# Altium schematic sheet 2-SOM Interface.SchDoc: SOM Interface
size B; CompanyName: NextGen RF Design; Address1: 2130 Howard Drive W; Address2: North Mankato, MN 56003; Address3: www.nextgenrf.com; Revision: 2; SheetNumber: 2; SheetTotal: 7; ProjName: BytePipe X9002_HDK
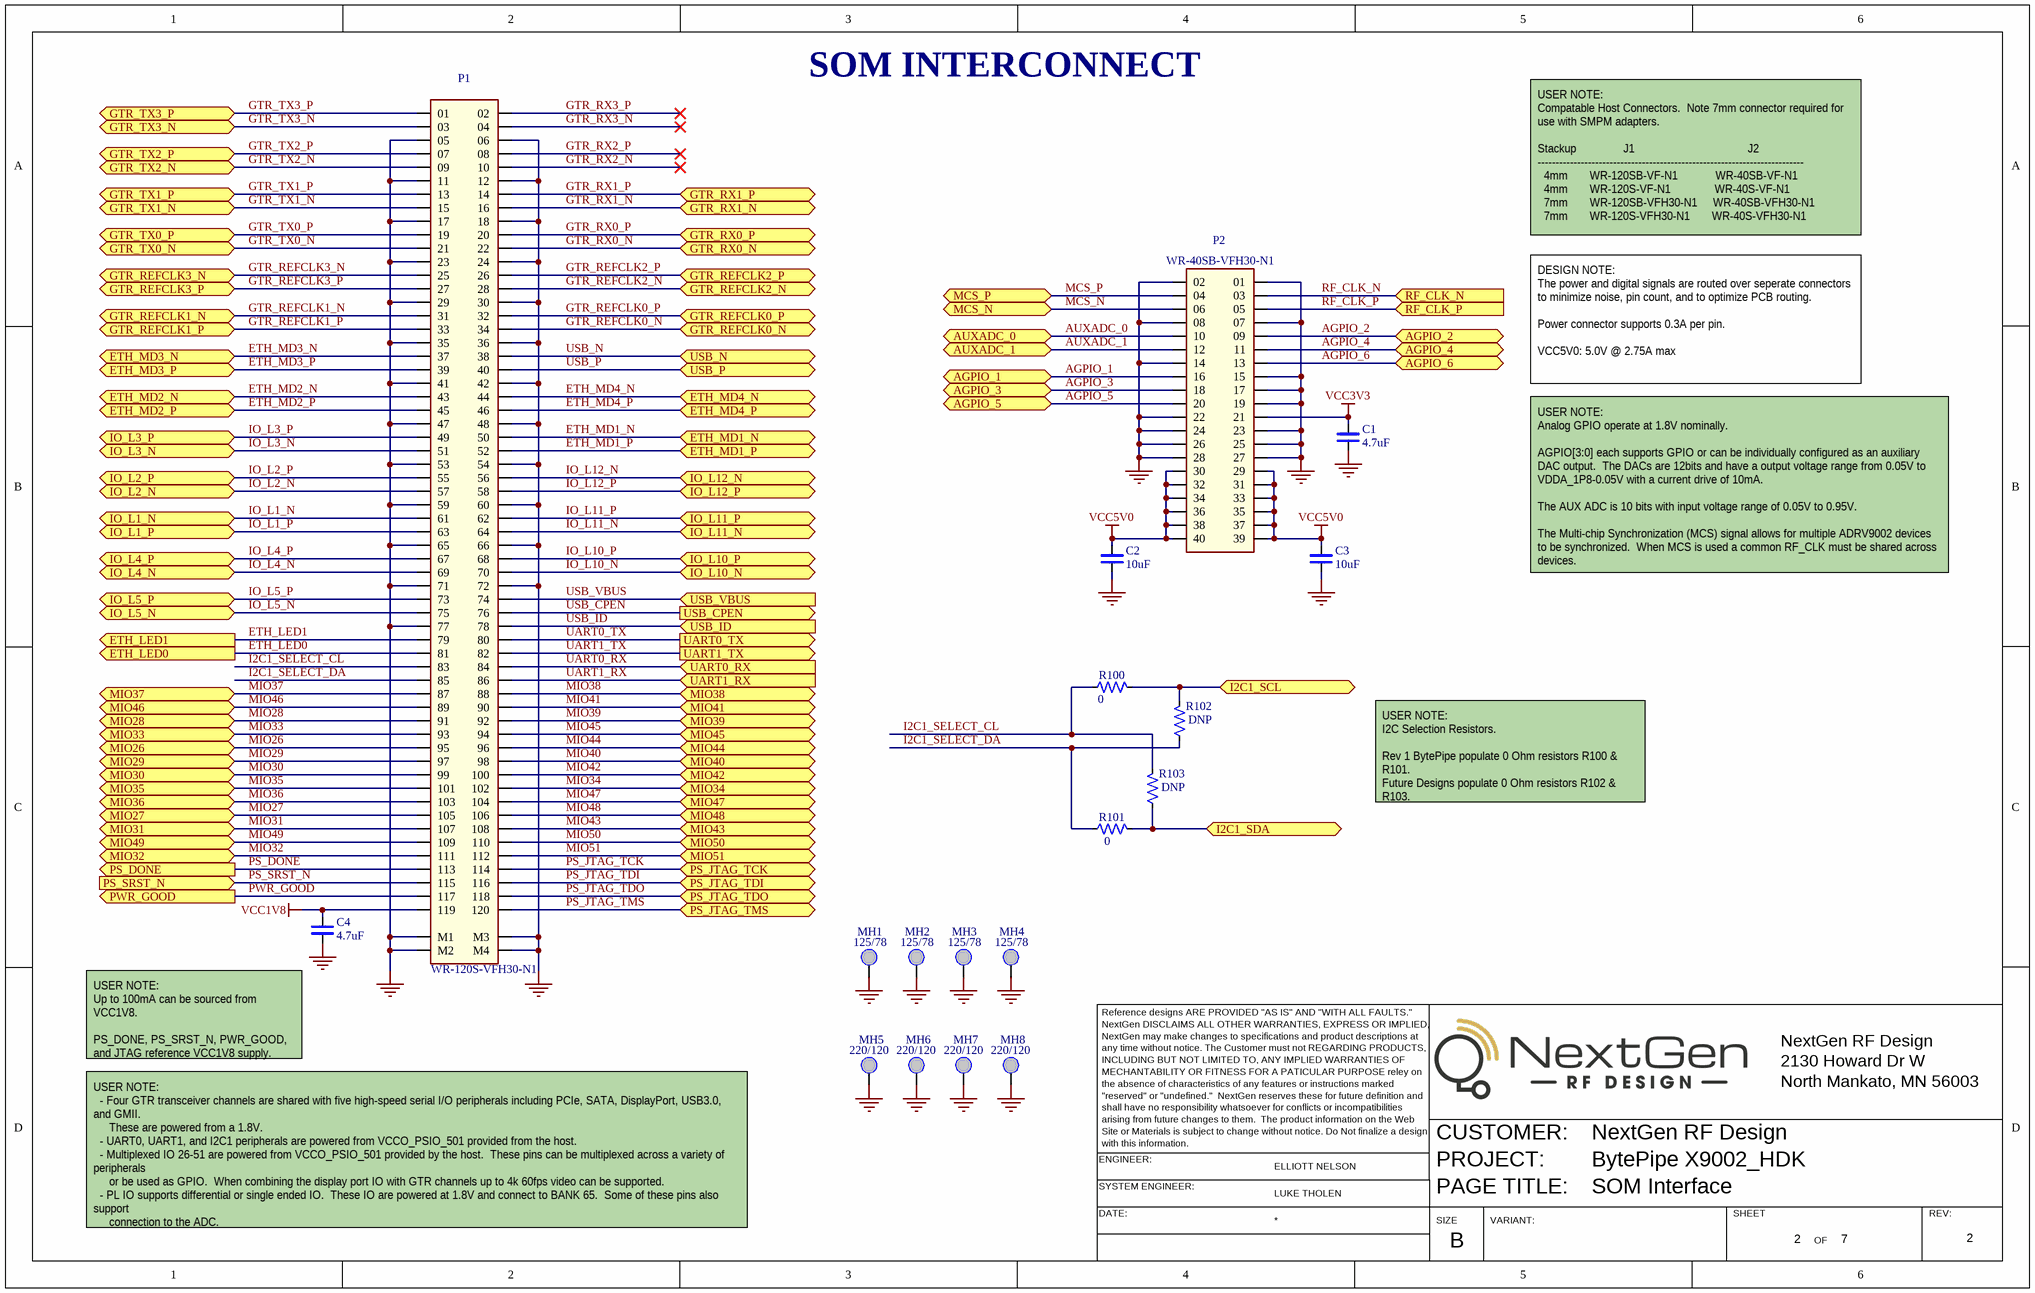
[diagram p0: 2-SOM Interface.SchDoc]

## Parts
C1  value 4.7uF  [SM/0402/CAP]  (hidden comment: CAP_CERAMIC_0402)
C2  value 10uF  [SM/0402/CAP]  (hidden comment: CAP_CERAMIC_0402)
C3  value 10uF  [SM/0402/CAP]  (hidden comment: CAP_CERAMIC_0402)
C4  value 4.7uF  [SM/0402/CAP]  (hidden comment: CAP_CERAMIC_0402)
MH1  HOLE_PTH_125/78  [MTG125/78]  (value not drawn)  (no BOM)
MH2  HOLE_PTH_125/78  [MTG125/78]  (value not drawn)  (no BOM)
MH3  HOLE_PTH_125/78  [MTG125/78]  (value not drawn)  (no BOM)
MH4  HOLE_PTH_125/78  [MTG125/78]  (value not drawn)  (no BOM)
MH5  HOLE_PTH_220/120  [MTG220/120]  (value not drawn)  (no BOM)
MH6  HOLE_PTH_220/120  [MTG220/120]  (value not drawn)  (no BOM)
MH7  HOLE_PTH_220/120  [MTG220/120]  (value not drawn)  (no BOM)
MH8  HOLE_PTH_220/120  [MTG220/120]  (value not drawn)  (no BOM)
P1  value WR-120S-VFH30-N1  [SM/CON/JAE/WR-120S-VFH30-N1]  (hidden comment: WR-120S-VFH30-N1‎)
P2  value WR-40SB-VFH30-N1  [SM/CON/JAE/WR-40SB-VFH30-N1]  (hidden comment: WR-40SB-VFH30-N1‎)
R100  value 0  [SM/0402/RES]  (hidden comment: RES_0402_A)
R101  value 0  [SM/0402/RES]  (hidden comment: RES_0402_A)
R102  value DNP  [SM/0402/RES]  (hidden comment: RES_0402_A)
R103  value DNP  [SM/0402/RES]  (hidden comment: RES_0402_A)

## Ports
AGPIO_1 (bidir), AGPIO_2 (bidir), AGPIO_3 (bidir), AGPIO_4 (bidir), AGPIO_5 (bidir), AGPIO_6 (bidir), AUXADC_0 (bidir), AUXADC_1 (bidir), ETH_LED0 (out), ETH_LED1 (out), ETH_MD1_N (bidir), ETH_MD1_P (bidir), ETH_MD2_N (bidir), ETH_MD2_P (bidir), ETH_MD3_N (bidir), ETH_MD3_P (bidir), ETH_MD4_N (bidir), ETH_MD4_P (bidir), GTR_REFCLK0_N (bidir), GTR_REFCLK0_P (bidir), GTR_REFCLK1_N (bidir), GTR_REFCLK1_P (bidir), GTR_REFCLK2_N (bidir), GTR_REFCLK2_P (bidir), GTR_REFCLK3_N (bidir), GTR_REFCLK3_P (bidir), GTR_RX0_N (bidir), GTR_RX0_P (bidir), GTR_RX1_N (bidir), GTR_RX1_P (bidir), GTR_TX0_N (bidir), GTR_TX0_P (bidir), GTR_TX1_N (bidir), GTR_TX1_P (bidir), GTR_TX2_N (bidir), GTR_TX2_P (bidir), GTR_TX3_N (bidir), GTR_TX3_P (bidir), I2C1_SCL (bidir), I2C1_SDA (bidir), IO_L1_N (bidir), IO_L1_P (bidir), IO_L2_N (bidir), IO_L2_P (bidir), IO_L3_N (bidir), IO_L3_P (bidir), IO_L4_N (bidir), IO_L4_P (bidir), IO_L5_N (bidir), IO_L5_P (bidir), IO_L10_N (bidir), IO_L10_P (bidir), IO_L11_N (bidir), IO_L11_P (bidir), IO_L12_N (bidir), IO_L12_P (bidir), MCS_N (bidir), MCS_P (bidir), MIO26 (bidir), MIO27 (bidir), MIO28 (bidir), MIO29 (bidir), MIO30 (bidir), MIO31 (bidir), MIO32 (bidir), MIO33 (bidir), MIO34 (bidir), MIO35 (bidir), MIO36 (bidir), MIO37 (bidir), MIO38 (bidir), MIO39 (bidir), MIO40 (bidir), MIO41 (bidir), MIO42 (bidir), MIO43 (bidir), MIO44 (bidir), MIO45 (bidir), MIO46 (bidir), MIO47 (bidir), MIO48 (bidir), MIO49 (bidir), MIO50 (bidir), MIO51 (bidir), PS_DONE (out), PS_JTAG_TCK (bidir), PS_JTAG_TDI (bidir), PS_JTAG_TDO (bidir), PS_JTAG_TMS (bidir), PS_SRST_N (in), PWR_GOOD (out), RF_CLK_N (in), RF_CLK_P (in), UART0_RX (in), UART0_TX (out), UART1_RX (in), UART1_TX (out), USB_CPEN (out), USB_ID (in), USB_N (bidir), USB_P (bidir), USB_VBUS (in)

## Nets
GND: C1.2(N2) C2.2(N2) C3.2(N2) C4.2(N2) MH1.1(N1) MH2.1(N1) MH3.1(N1) MH4.1(N1) MH5.1(N1) MH6.1(N1) MH7.1(N1) MH8.1(N1) P1.05 P1.06 P1.11 P1.12 P1.17 P1.18 P1.23 P1.24 P1.29 P1.30 P1.35 P1.36 P1.41 P1.42 P1.47 P1.48 P1.53 P1.54 P1.59 P1.60 P1.65 P1.66 P1.71 P1.72 P1.77 P1.M1 P1.M2 P1.M3 P1.M4 P2.01 P2.02 P2.07 P2.08 P2.14 P2.15 P2.17 P2.19 P2.22 P2.23 P2.24 P2.25 P2.26 P2.27 P2.28
VCC1V8: C4.1(N1) P1.119
VCC3V3: C1.1(N1) P2.21
VCC5V0: C2.1(N1) C3.1(N1) P2.29 P2.30 P2.31 P2.32 P2.33 P2.34 P2.35 P2.36 P2.37 P2.38 P2.39 P2.40
AGPIO_1: P2.16 ; port AGPIO_1
AGPIO_2: P2.09 ; port AGPIO_2
AGPIO_3: P2.18 ; port AGPIO_3
AGPIO_4: P2.11 ; port AGPIO_4
AGPIO_5: P2.20 ; port AGPIO_5
AGPIO_6: P2.13 ; port AGPIO_6
AUXADC_0: P2.10 ; port AUXADC_0
AUXADC_1: P2.12 ; port AUXADC_1
ETH_LED0: P1.81 ; port ETH_LED0
ETH_LED1: P1.79 ; port ETH_LED1
ETH_MD1_N: P1.50 ; port ETH_MD1_N
ETH_MD1_P: P1.52 ; port ETH_MD1_P
ETH_MD2_N: P1.43 ; port ETH_MD2_N
ETH_MD2_P: P1.45 ; port ETH_MD2_P
ETH_MD3_N: P1.37 ; port ETH_MD3_N
ETH_MD3_P: P1.39 ; port ETH_MD3_P
ETH_MD4_N: P1.44 ; port ETH_MD4_N
ETH_MD4_P: P1.46 ; port ETH_MD4_P
GTR_REFCLK0_N: P1.34 ; port GTR_REFCLK0_N
GTR_REFCLK0_P: P1.32 ; port GTR_REFCLK0_P
GTR_REFCLK1_N: P1.31 ; port GTR_REFCLK1_N
GTR_REFCLK1_P: P1.33 ; port GTR_REFCLK1_P
GTR_REFCLK2_N: P1.28 ; port GTR_REFCLK2_N
GTR_REFCLK2_P: P1.26 ; port GTR_REFCLK2_P
GTR_REFCLK3_N: P1.25 ; port GTR_REFCLK3_N
GTR_REFCLK3_P: P1.27 ; port GTR_REFCLK3_P
GTR_RX0_N: P1.22 ; port GTR_RX0_N
GTR_RX0_P: P1.20 ; port GTR_RX0_P
GTR_RX1_N: P1.16 ; port GTR_RX1_N
GTR_RX1_P: P1.14 ; port GTR_RX1_P
GTR_RX2_N: P1.10
GTR_RX2_P: P1.08
GTR_RX3_N: P1.04
GTR_RX3_P: P1.02
GTR_TX0_N: P1.21 ; port GTR_TX0_N
GTR_TX0_P: P1.19 ; port GTR_TX0_P
GTR_TX1_N: P1.15 ; port GTR_TX1_N
GTR_TX1_P: P1.13 ; port GTR_TX1_P
GTR_TX2_N: P1.09 ; port GTR_TX2_N
GTR_TX2_P: P1.07 ; port GTR_TX2_P
GTR_TX3_N: P1.03 ; port GTR_TX3_N
GTR_TX3_P: P1.01 ; port GTR_TX3_P
I2C1_SCL: R100.1 R102.1 ; port I2C1_SCL
I2C1_SDA: R101.1 R103.2 ; port I2C1_SDA
I2C1_SELECT_CL: P1.83 R100.2 R103.1
I2C1_SELECT_DA: P1.85 R101.2 R102.2
IO_L1_N: P1.61 ; port IO_L1_N
IO_L1_P: P1.63 ; port IO_L1_P
IO_L2_N: P1.57 ; port IO_L2_N
IO_L2_P: P1.55 ; port IO_L2_P
IO_L3_N: P1.51 ; port IO_L3_N
IO_L3_P: P1.49 ; port IO_L3_P
IO_L4_N: P1.69 ; port IO_L4_N
IO_L4_P: P1.67 ; port IO_L4_P
IO_L5_N: P1.75 ; port IO_L5_N
IO_L5_P: P1.73 ; port IO_L5_P
IO_L10_N: P1.70 ; port IO_L10_N
IO_L10_P: P1.68 ; port IO_L10_P
IO_L11_N: P1.64 ; port IO_L11_N
IO_L11_P: P1.62 ; port IO_L11_P
IO_L12_N: P1.56 ; port IO_L12_N
IO_L12_P: P1.58 ; port IO_L12_P
MCS_N: P2.06 ; port MCS_N
MCS_P: P2.04 ; port MCS_P
MIO26: P1.95 ; port MIO26
MIO27: P1.105 ; port MIO27
MIO28: P1.91 ; port MIO28
MIO29: P1.97 ; port MIO29
MIO30: P1.99 ; port MIO30
MIO31: P1.107 ; port MIO31
MIO32: P1.111 ; port MIO32
MIO33: P1.93 ; port MIO33
MIO34: P1.102 ; port MIO34
MIO35: P1.101 ; port MIO35
MIO36: P1.103 ; port MIO36
MIO37: P1.87 ; port MIO37
MIO38: P1.88 ; port MIO38
MIO39: P1.92 ; port MIO39
MIO40: P1.98 ; port MIO40
MIO41: P1.90 ; port MIO41
MIO42: P1.100 ; port MIO42
MIO43: P1.108 ; port MIO43
MIO44: P1.96 ; port MIO44
MIO45: P1.94 ; port MIO45
MIO46: P1.89 ; port MIO46
MIO47: P1.104 ; port MIO47
MIO48: P1.106 ; port MIO48
MIO49: P1.109 ; port MIO49
MIO50: P1.110 ; port MIO50
MIO51: P1.112 ; port MIO51
PS_DONE: P1.113 ; port PS_DONE
PS_JTAG_TCK: P1.114 ; port PS_JTAG_TCK
PS_JTAG_TDI: P1.116 ; port PS_JTAG_TDI
PS_JTAG_TDO: P1.118 ; port PS_JTAG_TDO
PS_JTAG_TMS: P1.120 ; port PS_JTAG_TMS
PS_SRST_N: P1.115 ; port PS_SRST_N
PWR_GOOD: P1.117 ; port PWR_GOOD
RF_CLK_N: P2.03 ; port RF_CLK_N
RF_CLK_P: P2.05 ; port RF_CLK_P
UART0_RX: P1.84 ; port UART0_RX
UART0_TX: P1.80 ; port UART0_TX
UART1_RX: P1.86 ; port UART1_RX
UART1_TX: P1.82 ; port UART1_TX
USB_CPEN: P1.76 ; port USB_CPEN
USB_ID: P1.78 ; port USB_ID
USB_N: P1.38 ; port USB_N
USB_P: P1.40 ; port USB_P
USB_VBUS: P1.74 ; port USB_VBUS

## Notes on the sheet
- SOM INTERCONNECT
- USER NOTE:
  Compatable Host Connectors.  Note 7mm connector required for use with SMPM adapters.
  Stackup               J1                                    J2
  --------------------------------------------------------------------------
  4mm       WR-120SB-VF-N1            WR-40SB-VF-N1
  4mm       WR-120S-VF-N1              WR-40S-VF-N1
  7mm       WR-120SB-VFH30-N1     WR-40SB-VFH30-N1
  7mm       WR-120S-VFH30-N1       WR-40S-VFH30-N1
- DESIGN NOTE:
  The power and digital signals are routed over seperate connectors to minimize noise, pin count, and to optimize PCB routing.
  Power connector supports 0.3A per pin.
  VCC5V0: 5.0V @ 2.75A max
- USER NOTE:
  Analog GPIO operate at 1.8V nominally.
  AGPIO[3:0] each supports GPIO or can be individually configured as an auxiliary DAC output.  The DACs are 12bits and have a output voltage range from 0.05V to VDDA_1P8-0.05V with a current drive of 10mA.
  The AUX ADC is 10 bits with input voltage range of 0.05V to 0.95V.
  The Multi-chip Synchronization (MCS) signal allows for multiple ADRV9002 devices to be synchronized.  When MCS is used a common RF_CLK must be shared across devices.
- USER NOTE:
  I2C Selection Resistors.
  Rev 1 BytePipe populate 0 Ohm resistors R100 & R101.
  Future Designs populate 0 Ohm resistors R102 & R103.
- Reference designs ARE PROVIDED "AS IS" AND "WITH ALL FAULTS."
- NextGen DISCLAIMS ALL OTHER WARRANTIES, EXPRESS OR IMPLIED,
- NextGen may make changes to specifications and product descriptions at
- NextGen RF Design
- (near C4) USER NOTE:
  Up to 100mA can be sourced from VCC1V8.
  PS_DONE, PS_SRST_N, PWR_GOOD, and JTAG reference VCC1V8 supply.
- any time without notice. The Customer must not REGARDING PRODUCTS,
- INCLUDING BUT NOT LIMITED TO, ANY IMPLIED WARRANTIES OF
- MECHANTABILITY OR FITNESS FOR A PATICULAR PURPOSE reley on
- "reserved" or "undefined."  NextGen reserves these for future definition and
- the absence of characteristics of any features or instructions marked
- shall have no responsibility whatsoever for conflicts or incompatibilities
- 2130 Howard Dr W
- North Mankato, MN 56003
- ENGINEER:
- Site or Materials is subject to change without notice. Do Not finalize a design
- with this information.
- arising from future changes to them.  The product information on the Web
- ELLIOTT NELSON
- CUSTOMER:
- PROJECT:
- USER NOTE:
  - Four GTR transceiver channels are shared with five high-speed serial I/O peripherals including PCIe, SATA, DisplayPort, USB3.0, and GMII.
  These are powered from a 1.8V.
  - UART0, UART1, and I2C1 peripherals are powered from VCCO_PSIO_501 provided from the host.
  - Multiplexed IO 26-51 are powered from VCCO_PSIO_501 provided by the host.  These pins can be multiplexed across a variety of peripherals
  or be used as GPIO.  When combining the display port IO with GTR channels up to 4k 60fps video can be supported.
  - PL IO supports differential or single ended IO.  These IO are powered at 1.8V and connect to BANK 65.  Some of these pins also support
  connection to the ADC.
  - USB OTG signals support USB2.0 host or device.  They can be combined with GTR channels to support USB 3.0.
- SYSTEM ENGINEER:
- DATE:
- LUKE THOLEN
- SIZE
- PAGE TITLE:
- VARIANT:
- SHEET
- OF
- REV:
- B

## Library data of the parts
C1 C4 = CAP_CERAMIC_0402: CAP CER 4.7UF 10V X5R 0402; TOL: ±20%; OEM#: CL05A475MP5NRNC; OEM NAME: Samsung
C2 C3 = CAP_CERAMIC_0402: 10µF ±20% 10V Ceramic Capacitor X5R 0402 (1005 Metric); OEM#: CL05A106MP8NUB8; OEM NAME: Samsung
MH1-MH4 = HOLE_PTH_125/78: 125 mil pad / 78 mil hole
MH5-MH8 = HOLE_PTH_220/120: 220 mil pad / 120 mil hole (#4 Pan Head Screw)
P1 = CON_JAE_WR-120S-VFH30-N1: 0.5 mm pitch, 120 Position Connector Receptacle, Center Strip Contacts Surface Mount Gold.; OEM NAME: JAE
P2 = CON_JAE_WR-40SB-VFH30-N1: 0.5 mm pitch, 40 Position Connector Receptacle, Center Strip Contacts Surface Mount Gold, with Alignment Pins.; OEM NAME: JAE
R100 R101 = RES_0402_A: RES SMD 0 OHM JUMPER 1/10W 0402; OEM#: ERJ-2GE0R00X; OEM NAME: Panasonic; TOL: 1%
R102 R103 = RES_0402_A: DNP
